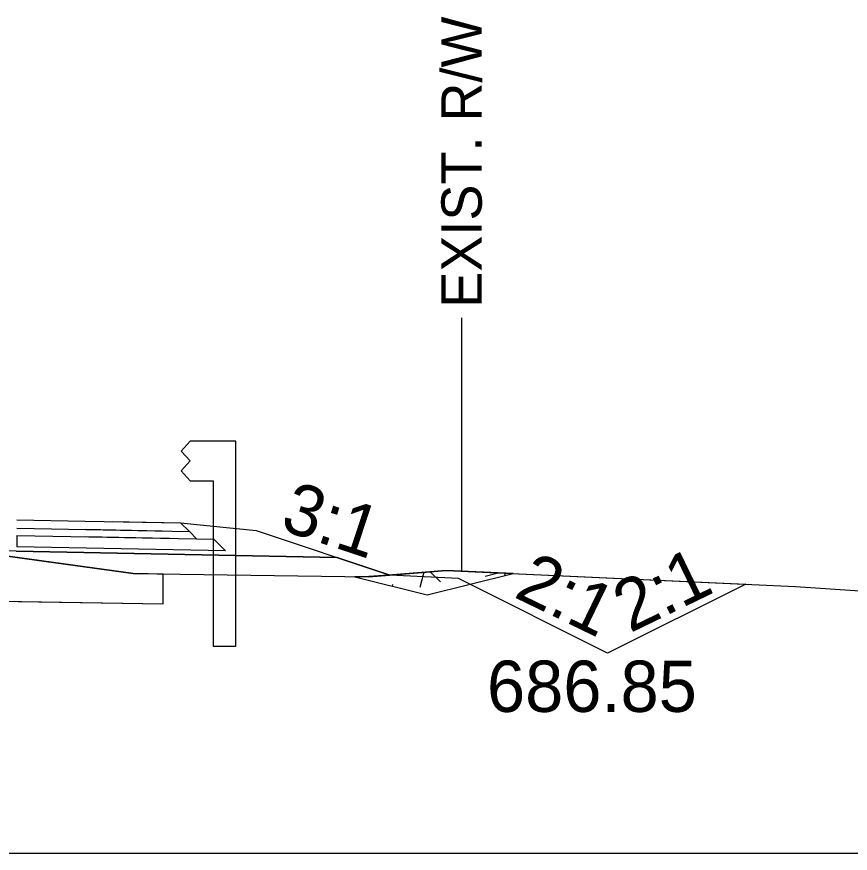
# Model space of a CAD drawing. Extents: x -26 to 4303, y -10 to 9577.
# Drawn here: x 3167 to 3191.36, y 2000 to 2024.46 of the extents above; entities that cross this region are included whole.
import ezdxf

# ---------------------------------------------------------------- set-up
doc = ezdxf.new("R2010")
doc.units = 0
for name, color, linetype in [('Old_Level_10', 7, 'Continuous'), ('Old_Level_2', 7, 'Continuous'), ('Pattern 3', 7, 'Continuous'), ('Prop CMT Concrete Wall', 7, 'Continuous'), ('Prop CMT Pvmt Course 1', 7, 'Continuous'), ('Prop CMT Pvmt Course 2', 7, 'Continuous'), ('Prop CMT Pvmt Course 2 Wedge', 7, 'Continuous'), ('Prop CMT Pvmt Course 3', 7, 'Continuous'), ('Prop CMT Pvmt Course 3 Wedge', 7, 'Continuous'), ('Prop CMT Pvmt Wedge Surface 1', 7, 'Continuous'), ('Prop CMT Shld Paved Course 2', 7, 'Continuous'), ('Prop CMT Slope Grass', 7, 'Continuous'), ('Prop CMT Subgrade Earthwork', 7, 'Continuous'), ('Prop Road Sect_ Recs - UC Shallow (Outline)', 7, 'Continuous'), ('Prop Shade Light', 7, 'Continuous'), ('Prop XS DDE Elevations', 7, 'Continuous'), ('Prop XS Ditch Standard Text', 7, 'Continuous'), ('Prop XS Earthwork Shape', 7, 'Continuous'), ('Prop XS Side Slope Text', 7, 'Continuous')]:
    doc.layers.add(name, color=color, linetype=linetype)

msp = doc.modelspace()

# ---------------------------------------------------------------- linework, layer by layer
at = {"layer": 'Old_Level_10'}
for p, q in [((3179.909, 2008.031), (3177.909, 2008.131)), ((3184.27, 2005.85), (3179.909, 2008.031)), ((3188.305, 2007.867), (3184.27, 2005.85))]:
    msp.add_line(p, q, dxfattribs=at)
at = {"layer": 'Old_Level_2'}
msp.add_line((3150, 2000), (3300, 2000), dxfattribs=at)
msp.add_line((3150, 2000), (3300, 2000), dxfattribs=at)
at = {"layer": 'Pattern 3'}
for p, q in [((3176.999, 2008.082), (3177.026, 2008.055)), ((3178.897, 2008.215), (3178.779, 2007.774)), ((3179.088, 2008.231), (3179.383, 2007.936)), ((3180.694, 2008.098), (3181.073, 2008.2)), ((3181.279, 2008.19), (3181.259, 2008.118)), ((3181.371, 2008.186), (3181.403, 2008.154)), ((3177.984, 2007.863), (3177.97, 2007.811))]:
    msp.add_line(p, q, dxfattribs=at)
msp.add_lwpolyline([(3179, 2007.553), (3181.506, 2008.18), (3179.547, 2008.27), (3177.868, 2008.128), (3177.141, 2008.08), (3176.878, 2008.084)], close=True, dxfattribs=at)
at = {"layer": 'Prop CMT Pvmt Course 1'}
msp.add_lwpolyline([(3167, 2009.295), (3167, 2008.962)], dxfattribs=at)
at = {"layer": 'Prop CMT Pvmt Course 2'}
for points in [[(3169.791, 2009.698), (3171.791, 2009.658), (3172.046, 2009.403)], [(3171.255, 2009.418), (3169, 2009.463)]]:
    msp.add_lwpolyline(points, dxfattribs=at)
at = {"layer": 'Prop CMT Pvmt Course 2 Wedge'}
msp.add_line((3171.791, 2009.658), (3174, 2009.433), dxfattribs=at)
msp.add_lwpolyline([(3174, 2009.433), (3177.909, 2008.131)], dxfattribs=at)
at = {"layer": 'Prop CMT Pvmt Course 3'}
for points in [[(3167, 2009.503), (3172.046, 2009.403), (3172.258, 2009.19)], [(3171.468, 2009.206), (3169, 2009.255)]]:
    msp.add_lwpolyline(points, dxfattribs=at)
at = {"layer": 'Prop CMT Pvmt Course 3 Wedge'}
for points in [[(3173.405, 2012.053), (3172.072, 2012.053), (3171.801, 2011.761)], [(3173.405, 2006.053), (3173.405, 2012.053)], [(3171.801, 2011.761), (3172.072, 2011.469)], [(3172.072, 2011.469), (3171.801, 2011.178)], [(3171.801, 2011.178), (3172.072, 2010.886), (3172.738, 2010.886)], [(3172.738, 2010.886), (3172.738, 2006.053)], [(3172.738, 2006.053), (3173.405, 2006.053)]]:
    msp.add_lwpolyline(points, dxfattribs=at)
at = {"layer": 'Prop CMT Pvmt Wedge Surface 1'}
msp.add_line((3166.982, 2008.837), (3176.352, 2008.649), dxfattribs=at)
at = {"layer": 'Prop CMT Shld Paved Course 2'}
for points in [[(3167, 2009.753), (3169, 2009.713)], [(3169, 2009.713), (3171.791, 2009.658)]]:
    msp.add_lwpolyline(points, dxfattribs=at)
at = {"layer": 'Prop CMT Slope Grass'}
msp.add_lwpolyline([(3164.11, 2009.045), (3170.399, 2008.178), (3177.285, 2008.078), (3179.547, 2008.269), (3189.762, 2007.801), (3191.652, 2007.673)], dxfattribs=at)
at = {"layer": 'Prop CMT Subgrade Earthwork'}
for points in [[(3167, 2009.295), (3172.258, 2009.19), (3172.758, 2009.18), (3173.098, 2008.84)], [(3173.098, 2008.84), (3167, 2008.962)]]:
    msp.add_lwpolyline(points, dxfattribs=at)
at = {"layer": 'Prop Road Sect_ Recs - UC Shallow (Outline)'}
msp.add_line((3163.573, 2007.42), (3171.278, 2007.293), dxfattribs=at)
msp.add_lwpolyline([(3163.573, 2007.42), (3171.278, 2007.293), (3171.278, 2008.165), (3170.399, 2008.178), (3165.037, 2008.918), (3163.573, 2008.92)], close=True, dxfattribs=at)
at = {"layer": 'Prop Shade Light'}
for p, q in [((3170.399, 2008.178), (3165.001, 2008.923)), ((3163.573, 2007.42), (3171.278, 2007.293))]:
    msp.add_line(p, q, dxfattribs=at)
msp.add_lwpolyline([(3171.278, 2007.293), (3171.278, 2008.165), (3170.399, 2008.178)], dxfattribs=at)
at = {"layer": 'Prop XS DDE Elevations'}
msp.add_lwpolyline([(3177.285, 2008.078), (3177.909, 2008.131), (3176.352, 2008.649), (3166.982, 2008.837), (3165.391, 2008.869), (3170.399, 2008.178)], close=True, dxfattribs=at)
at = {"layer": 'Prop XS Ditch Standard Text'}
msp.add_line((3180, 2015.65), (3180, 2008.248), dxfattribs=at)
at = {"layer": 'Prop XS Earthwork Shape'}
msp.add_lwpolyline([(3188.305, 2007.867), (3184.27, 2005.85), (3179.909, 2008.031), (3177.909, 2008.131), (3179.547, 2008.269)], close=True, dxfattribs=at)

# ---------------------------------------------------------------- texts
at = {"layer": 'Prop CMT Concrete Wall'}
for rotation, p in [(25.8617, (3184.923, 2006.431)), (334.1383, (3181.492, 2007.507))]:
    msp.add_text('2:1', height=1.5, rotation=rotation, dxfattribs=at).set_placement(p)
msp.add_text('686.85', height=1.5, dxfattribs=at).set_placement((3180.743, 2004.133))
at = {"layer": 'Prop XS Ditch Standard Text'}
msp.add_text('EXIST. R/W', height=1.1811, rotation=90, dxfattribs=at).set_placement((3180.591, 2015.952))
at = {"layer": 'Prop XS Side Slope Text'}
msp.add_text('3:1', height=1.5, rotation=341.7233, dxfattribs=at).set_placement((3174.655, 2009.476))

doc.saveas('drawing.dxf')
